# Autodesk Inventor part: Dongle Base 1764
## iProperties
Created: 2010-01
Part Number: Dongle Base 1764
Document SubType Name: Modeling
Designer: jgehrig
Density: 1 g/cm^3
Author: jgehrig
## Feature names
1. Extrusion1
2. Fillet1
3. Shell1
4. Extrusion2
5. Extrusion3
6. Extrusion4
